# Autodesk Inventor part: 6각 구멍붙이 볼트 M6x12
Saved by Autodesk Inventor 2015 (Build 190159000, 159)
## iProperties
Created: 2025-06
Part Number: 6각 구멍붙이 볼트 M6x12
Material: 일반
Document SubType Name: Modeling
Designer: 104
Density: 1 g/cm^3
Appearance: 기본값
Author: 104
Author: jhkim
Description: 6각머리 태핑 나사
Creation Date: 2025-05-23
Sending System: Autodesk Inventor 2026
Preprocessor: ST-DEVELOPER v20.1
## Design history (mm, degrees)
node "6각 구멍붙이 볼트 M6x121"
body "Solid1"
node "기준1"
